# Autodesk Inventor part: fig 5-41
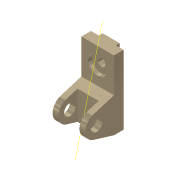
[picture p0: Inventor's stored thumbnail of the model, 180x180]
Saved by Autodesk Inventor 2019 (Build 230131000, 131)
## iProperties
Shininess: 65.0
Angle Display Precision: 2
Document Length Units: 11269
Document Angle Units: 11279
Document Time Units: 11290
Document Mass Units: 11283
Document Length Units Precision: 3
Document Angle Units Precision: 2
Created: 2001-11
Part Number: fig 5-41
Document SubType Name: Modeling
Designer: Renu Muthoo
Density: 1 g/cm^3
Material: Generic
Appearance: Metal-Titanium (Polished)
Density: 0.0
Volumn: 0.0
Area: 0.0
PropertySet Name: Model Information
Control State: 0
Master: False
Checked Out: False
Author: Renu Muthoo
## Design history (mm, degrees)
node "Sketch1"
sketch "Sketch2"
  geometry: L1 (33.257, 104.664)-(33.257, -75.336); L2 (33.257, -75.336)-(8.257, -75.336); L3 (8.257, -75.336)-(-45.451, -59.045); L4 (-45.451, -1.628)-(8.257, 14.664); L5 (8.257, 14.664)-(8.257, 104.664); L6 (8.257, 104.664)-(33.257, 104.664); C1 r 15 at (-36.743, -30.336); A1 r 30 centre (-36.743, -30.336) between (-45.451, -1.628) and (-45.451, -59.045)
  constraints: 12 end point, 2 centre point, 2 equal length, 2 parallel, 2 point on circle, 2 tangent, 1 coincident, 1 perpendicular, 1 vertical
  dimensions: "d0" = 180 distance of L1.start L1.end; "d1" = 30 radius of A1; "d2" = 25 distance of L5.end L1.start; "d3" = 45 distance from line of L2 A1.centre; "d4" = 70 distance from line of L1 A1.centre; "d5" = 30 diameter of C1
extrude "Extrusion1" new body sketch "Sketch2" distance "d6" = 85; taper "d7" = 0 deg
workplane "Work Plane1"
sketch "Sketch3"
  geometry: L1 (15, 62.364)-(70, 62.364); L2 (70, 62.364)-(70, -52.386); L3 (70, -52.386)-(15, -52.386); L4 (15, -52.386)-(15, 62.364); L5 (0, -45)-(0, -28.708) reference
  constraints: 8 end point, 2 parallel, 1 horizontal, 1 perpendicular
  dimensions: "d8" = 55 distance of L1.start L1.end; "d9" = 15 distance between parallel lines of L5 L4
extrude "Extrusion2" cut sketch "Sketch3" distance "d10" = 50; taper "d11" = 0 deg
sketch "Sketch4"
  geometry: L1 (0, 25)-(85, 25) reference; L2 (0, 0)-(0, 25) reference; L3 (20, 25)-(65, 25); L4 (65, 25)-(65, 35); L5 (65, 35)-(20, 35); L6 (20, 35)-(20, 25)
  constraints: 8 end point, 2 parallel, 1 horizontal, 1 perpendicular, 1 point on line
  dimensions: "d12" = 45 distance of L4.end L5.end; "d13" = 10 distance of L3.end L4.end; "d14" = 20 distance between parallel lines of L2 L6
extrude "Extrusion3" join sketch "Sketch4" stored distance "d15" = 50; taper "d16" = 0 deg
sketch "Sketch5"
  geometry: L1 (85, 0)-(85, 90) reference; L2 (0, 90)-(85, 90) reference; 1 further point
  dimensions: "d17" = 42 distance from line of L2 point (42.5, 48); "d18" = 42.5 distance from line of L1 point (42.5, 48)
hole "Hole1" sketch "Sketch5" at (42.5, 48) diameter "d19" = 20; stored, may be unused: countersink angle "d23" = 82 deg, drill point angle "d25" = 118 deg; dims "d20" = 6, "d21" = 50, "d22" = 10, "d24" = 8
workaxis "Work Axis1"
body "Solid1"
